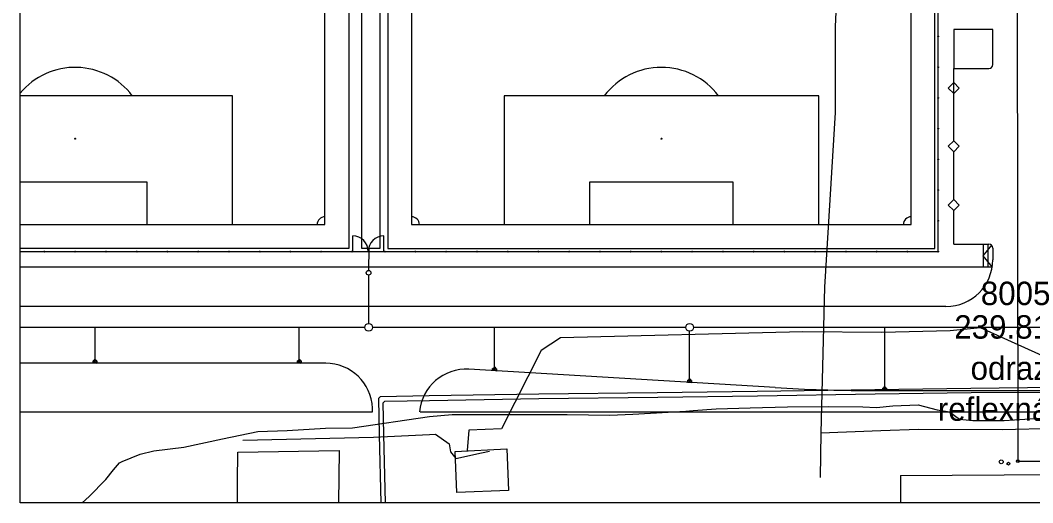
# Model space of a CAD drawing. Extents: x -264090 to -263500, y -1242327 to -1242030.
# Drawn here: x -264089.7 to -263959.9, y -1242326.6 to -1242264.8 of the extents above; entities that cross this region are included whole.
import ezdxf

# ---------------------------------------------------------------- set-up
doc = ezdxf.new("R2010")
doc.units = 0
for name, color, linetype in [('KFA_KOORD_SIT_a_IS_SEDA', 7, 'Continuous'), ('KFA_ZVS_BOD_CISLO', 7, 'Continuous'), ('KFA_ZVS_BOD_VYSKA', 7, 'Continuous'), ('KFA_ZVS_POPIS', 7, 'Continuous'), ('RAM_NA_TLAC', 7, 'Continuous')]:
    doc.layers.add(name, color=color, linetype=linetype)

msp = doc.modelspace()

# ---------------------------------------------------------------- linework, layer by layer
at = {"layer": 'KFA_KOORD_SIT_a_IS_SEDA'}
for p, q in [((-264047.57, -1242187.93), (-264047.57, -1242294.03)), ((-264050.62, -1242290.98), (-264050.62, -1242190.98)), ((-264039.52, -1242190.98), (-264039.52, -1242290.98)), ((-263975.52, -1242290.98), (-263975.52, -1242190.98)), ((-264045.93, -1242194.98), (-264045.93, -1242293.98)), ((-264043.53, -1242293.98), (-264043.53, -1242194.98)), ((-263984.63, -1242252.16), (-263985.27, -1242265.6)), ((-263972.07, -1242294.43), (-263972.07, -1242255.06)), ((-263961.97, -1242257), (-263961.85, -1242321.3)), ((-263985.27, -1242265.6), (-263985.24, -1242276.61)), ((-263972.13, -1242266.87), (-263972.01, -1242266.87)), ((-263972.07, -1242266.93), (-263972.07, -1242266.81)), ((-263965.07, -1242265.98), (-263970.07, -1242265.98)), ((-263965.07, -1242270.48), (-263965.07, -1242265.98)), ((-263972.13, -1242270.81), (-263972.01, -1242270.81)), ((-263972.07, -1242270.87), (-263972.07, -1242270.75)), ((-263970.06, -1242280.24), (-263970.07, -1242270.98)), ((-264062.46, -1242274.48), (-264089.66, -1242274.48)), ((-264062.46, -1242290.98), (-264062.46, -1242274.48)), ((-263987.36, -1242274.48), (-264027.68, -1242274.48)), ((-264027.68, -1242274.48), (-264027.68, -1242290.98)), ((-263987.36, -1242290.98), (-263987.36, -1242274.48)), ((-263972.13, -1242274.74), (-263972.01, -1242274.74)), ((-263972.07, -1242274.8), (-263972.07, -1242274.68)), ((-263985.24, -1242276.61), (-263986.63, -1242298.98)), ((-263972.13, -1242278.68), (-263972.01, -1242278.68)), ((-263972.07, -1242278.74), (-263972.07, -1242278.62)), ((-263972.13, -1242282.62), (-263972.01, -1242282.62)), ((-263972.07, -1242282.68), (-263972.07, -1242282.56)), ((-263970.07, -1242287.78), (-263970.07, -1242281.65)), ((-264089.66, -1242285.48), (-264073.46, -1242285.48)), ((-264073.46, -1242285.48), (-264073.46, -1242290.98)), ((-264016.68, -1242290.98), (-264016.68, -1242285.48)), ((-264016.68, -1242285.48), (-263998.36, -1242285.48)), ((-263998.36, -1242285.48), (-263998.36, -1242290.98)), ((-263972.13, -1242286.56), (-263972.01, -1242286.56)), ((-263972.07, -1242286.62), (-263972.07, -1242286.5)), ((-263970.07, -1242293.48), (-263970.07, -1242289.19)), ((-263972.13, -1242290.49), (-263972.01, -1242290.49)), ((-263972.07, -1242290.55), (-263972.07, -1242290.43)), ((-264089.66, -1242290.98), (-264050.62, -1242290.98)), ((-264039.52, -1242290.98), (-263975.52, -1242290.98)), ((-264047.07, -1242294.43), (-264047.07, -1242292.43)), ((-264043.07, -1242294.43), (-264043.07, -1242292.43)), ((-264047.57, -1242294.03), (-264089.66, -1242294.03)), ((-264089.66, -1242294.03), (-264089.66, -1242294.03)), ((-264089.66, -1242294.43), (-264045.12, -1242294.43)), ((-264086.5, -1242294.43), (-264086.62, -1242294.43)), ((-264086.56, -1242294.49), (-264086.56, -1242294.37)), ((-264082.56, -1242294.43), (-264082.68, -1242294.43)), ((-264082.62, -1242294.49), (-264082.62, -1242294.37)), ((-264078.62, -1242294.43), (-264078.74, -1242294.43)), ((-264078.68, -1242294.49), (-264078.68, -1242294.37)), ((-264074.68, -1242294.43), (-264074.8, -1242294.43)), ((-264074.74, -1242294.49), (-264074.74, -1242294.37)), ((-264070.74, -1242294.43), (-264070.86, -1242294.43)), ((-264070.8, -1242294.49), (-264070.8, -1242294.37)), ((-264066.8, -1242294.43), (-264066.92, -1242294.43)), ((-264066.86, -1242294.49), (-264066.86, -1242294.37)), ((-264062.86, -1242294.43), (-264062.98, -1242294.43)), ((-264062.92, -1242294.49), (-264062.92, -1242294.37)), ((-264058.92, -1242294.43), (-264059.04, -1242294.43)), ((-264058.98, -1242294.49), (-264058.98, -1242294.37)), ((-264054.99, -1242294.43), (-264055.11, -1242294.43)), ((-264055.05, -1242294.49), (-264055.05, -1242294.37)), ((-264051.05, -1242294.43), (-264051.17, -1242294.43)), ((-264051.11, -1242294.49), (-264051.11, -1242294.37)), ((-264047.11, -1242294.43), (-264047.23, -1242294.43)), ((-264047.17, -1242294.49), (-264047.17, -1242294.37)), ((-264045.93, -1242293.98), (-264043.53, -1242293.98)), ((-264045.57, -1242294.43), (-264044.57, -1242294.43)), ((-264045.12, -1242294.43), (-263972.07, -1242294.43)), ((-264045.02, -1242293.98), (-264045.03, -1242296.85)), ((-264042.91, -1242294.43), (-264043.03, -1242294.43)), ((-264042.97, -1242294.49), (-264042.97, -1242294.37)), ((-264038.97, -1242294.43), (-264039.09, -1242294.43)), ((-264039.03, -1242294.49), (-264039.03, -1242294.37)), ((-264035.03, -1242294.43), (-264035.15, -1242294.43)), ((-264035.09, -1242294.49), (-264035.09, -1242294.37)), ((-264031.09, -1242294.43), (-264031.21, -1242294.43)), ((-264031.15, -1242294.49), (-264031.15, -1242294.37)), ((-264027.15, -1242294.43), (-264027.27, -1242294.43)), ((-264027.21, -1242294.49), (-264027.21, -1242294.37)), ((-264023.21, -1242294.43), (-264023.33, -1242294.43)), ((-264023.27, -1242294.49), (-264023.27, -1242294.37)), ((-264019.27, -1242294.43), (-264019.39, -1242294.43)), ((-264019.33, -1242294.49), (-264019.33, -1242294.37)), ((-264015.34, -1242294.43), (-264015.46, -1242294.43)), ((-264015.4, -1242294.49), (-264015.4, -1242294.37)), ((-264011.4, -1242294.43), (-264011.52, -1242294.43)), ((-264011.46, -1242294.49), (-264011.46, -1242294.37)), ((-264007.46, -1242294.43), (-264007.58, -1242294.43)), ((-264007.52, -1242294.49), (-264007.52, -1242294.37)), ((-264003.52, -1242294.43), (-264003.64, -1242294.43)), ((-264003.58, -1242294.49), (-264003.58, -1242294.37)), ((-263999.58, -1242294.43), (-263999.7, -1242294.43)), ((-263999.64, -1242294.49), (-263999.64, -1242294.37)), ((-263995.64, -1242294.43), (-263995.76, -1242294.43)), ((-263995.7, -1242294.49), (-263995.7, -1242294.37)), ((-263991.7, -1242294.43), (-263991.82, -1242294.43)), ((-263991.76, -1242294.49), (-263991.76, -1242294.37)), ((-263987.76, -1242294.43), (-263987.88, -1242294.43)), ((-263987.82, -1242294.49), (-263987.82, -1242294.37)), ((-263983.82, -1242294.43), (-263983.94, -1242294.43)), ((-263983.88, -1242294.49), (-263983.88, -1242294.37)), ((-263979.89, -1242294.43), (-263980.01, -1242294.43)), ((-263979.95, -1242294.49), (-263979.95, -1242294.37)), ((-263975.95, -1242294.43), (-263976.07, -1242294.43)), ((-263976.01, -1242294.49), (-263976.01, -1242294.37)), ((-263972.13, -1242294.43), (-263972.01, -1242294.43)), ((-263972.07, -1242294.49), (-263972.07, -1242294.37)), ((-263970.07, -1242293.48), (-263965.57, -1242293.48)), ((-263966.31, -1242293.48), (-263966.31, -1242296.43)), ((-263965.68, -1242293.48), (-263965.68, -1242296.43)), ((-263965.07, -1242293.98), (-263965.07, -1242295.48)), ((-264045.03, -1242297.45), (-264045.03, -1242303.65)), ((-263986.63, -1242298.98), (-263987.11, -1242317.68)), ((-263971.07, -1242301.48), (-264089.66, -1242301.48)), ((-264045.53, -1242304.15), (-264089.66, -1242304.15)), ((-264080.08, -1242308.24), (-264080.08, -1242304.15)), ((-264053.91, -1242308.24), (-264053.91, -1242304.15)), ((-264004.4, -1242304.15), (-264044.53, -1242304.15)), ((-264028.9, -1242309.22), (-264028.89, -1242304.15)), ((-263989.39, -1242304.73), (-264020.46, -1242305.5)), ((-264003.9, -1242310.72), (-264003.9, -1242304.65)), ((-263954.41, -1242304.15), (-264003.4, -1242304.15)), ((-263979.27, -1242304.82), (-263989.39, -1242304.73)), ((-263970.54, -1242304.6), (-263979.27, -1242304.82)), ((-263978.91, -1242311.74), (-263978.91, -1242304.15)), ((-263966.62, -1242304.22), (-263970.54, -1242304.6)), ((-263946.96, -1242313.09), (-263966.62, -1242304.22)), ((-264020.46, -1242305.5), (-264022.91, -1242307.11)), ((-264022.91, -1242307.11), (-264028.02, -1242317.15)), ((-264080.33, -1242308.44), (-264079.83, -1242308.44)), ((-264080.33, -1242308.73), (-264080.33, -1242308.44)), ((-264080.33, -1242308.44), (-264079.83, -1242308.73)), ((-264080.33, -1242308.44), (-264079.83, -1242308.73)), ((-264079.83, -1242308.44), (-264080.33, -1242308.44)), ((-264079.83, -1242308.44), (-264079.83, -1242308.73)), ((-264079.83, -1242308.73), (-264079.83, -1242308.44)), ((-264054.16, -1242308.44), (-264053.66, -1242308.44)), ((-264054.16, -1242308.73), (-264054.16, -1242308.44)), ((-264054.16, -1242308.44), (-264053.66, -1242308.73)), ((-264054.16, -1242308.44), (-264053.66, -1242308.73)), ((-264053.66, -1242308.44), (-264054.16, -1242308.44)), ((-264053.66, -1242308.44), (-264053.66, -1242308.73)), ((-264053.66, -1242308.73), (-264053.66, -1242308.44)), ((-264050.53, -1242308.73), (-264089.66, -1242308.73)), ((-264079.83, -1242308.73), (-264080.33, -1242308.73)), ((-264053.66, -1242308.73), (-264054.16, -1242308.73)), ((-263992.94, -1242311.87), (-264032.17, -1242309.51)), ((-264032.17, -1242309.51), (-264032.17, -1242309.51)), ((-264029.16, -1242309.69), (-264029.14, -1242309.41)), ((-264028.66, -1242309.72), (-264029.16, -1242309.69)), ((-264029.14, -1242309.41), (-264028.65, -1242309.44)), ((-264029.14, -1242309.41), (-264028.66, -1242309.72)), ((-264029.14, -1242309.41), (-264028.66, -1242309.72)), ((-264028.65, -1242309.44), (-264029.14, -1242309.41)), ((-264028.65, -1242309.44), (-264028.66, -1242309.72)), ((-264028.66, -1242309.72), (-264028.65, -1242309.44)), ((-264004.16, -1242311.2), (-264004.15, -1242310.91)), ((-264003.66, -1242311.23), (-264004.16, -1242311.2)), ((-264004.15, -1242310.91), (-264003.65, -1242310.94)), ((-264004.15, -1242310.91), (-264003.66, -1242311.23)), ((-264004.15, -1242310.91), (-264003.66, -1242311.23)), ((-264003.65, -1242310.94), (-264004.15, -1242310.91)), ((-264003.65, -1242310.94), (-264003.66, -1242311.23)), ((-264003.66, -1242311.23), (-264003.65, -1242310.94)), ((-264008.06, -1242312.52), (-264023.23, -1242312.7)), ((-263995.27, -1242312.37), (-264008.06, -1242312.52)), ((-263980.16, -1242312.16), (-263995.27, -1242312.37)), ((-263980.94, -1242312.23), (-263857.33, -1242312.23)), ((-263967.86, -1242311.99), (-263980.16, -1242312.16)), ((-263980.14, -1242312.68), (-263967.84, -1242312.51)), ((-263979.16, -1242311.94), (-263978.66, -1242311.94)), ((-263979.16, -1242312.23), (-263979.16, -1242311.94)), ((-263979.16, -1242311.94), (-263978.66, -1242312.23)), ((-263979.16, -1242311.94), (-263978.66, -1242312.23)), ((-263978.66, -1242311.94), (-263979.16, -1242311.94)), ((-263978.66, -1242312.23), (-263979.16, -1242312.23)), ((-263978.66, -1242311.94), (-263978.66, -1242312.23)), ((-263978.66, -1242312.23), (-263978.66, -1242311.94)), ((-263956.22, -1242311.84), (-263967.86, -1242311.99)), ((-263967.84, -1242312.51), (-263955.67, -1242312.42)), ((-264043.54, -1242313.06), (-264043.78, -1242313.27)), ((-264043.78, -1242313.27), (-264043.67, -1242317.93)), ((-264037.28, -1242312.92), (-264043.54, -1242313.06)), ((-264043.16, -1242313.81), (-264042.95, -1242313.61)), ((-264043.1, -1242317.89), (-264043.16, -1242313.81)), ((-264042.95, -1242313.61), (-264037.23, -1242313.51)), ((-264023.23, -1242312.7), (-264037.28, -1242312.92)), ((-264037.23, -1242313.51), (-264023.21, -1242313.28)), ((-264023.21, -1242313.28), (-264007.99, -1242313.07)), ((-264007.99, -1242313.07), (-263995.2, -1242312.9)), ((-263995.2, -1242312.9), (-263980.14, -1242312.68)), ((-264089.66, -1242314.98), (-264044.53, -1242314.98)), ((-264044.53, -1242314.98), (-264044.53, -1242314.48)), ((-264038.44, -1242314.98), (-263836.4, -1242314.98)), ((-264011.19, -1242315.25), (-264004.4, -1242314.87)), ((-264004.4, -1242314.87), (-264003.44, -1242314.8)), ((-264003.44, -1242314.8), (-264000.5, -1242314.59)), ((-264000.5, -1242314.59), (-263996.15, -1242314.45)), ((-263996.15, -1242314.45), (-263991.36, -1242314.31)), ((-263991.36, -1242314.31), (-263986.12, -1242314.3)), ((-263986.12, -1242314.3), (-263981.72, -1242314.33)), ((-263981.72, -1242314.33), (-263979.98, -1242314.43)), ((-263979.98, -1242314.43), (-263977.86, -1242314.19)), ((-263977.86, -1242314.19), (-263974.61, -1242314.09)), ((-263974.61, -1242314.09), (-263972.17, -1242314.7)), ((-263972.17, -1242314.7), (-263970.63, -1242314.99)), ((-263970.63, -1242314.99), (-263969.31, -1242315.89)), ((-264047.11, -1242317.03), (-264037.23, -1242315.56)), ((-264037.23, -1242315.56), (-264034.31, -1242315.31)), ((-264034.31, -1242315.31), (-264029.89, -1242315.32)), ((-264029.89, -1242315.32), (-264024.65, -1242315.29)), ((-264024.65, -1242315.29), (-264019.6, -1242315.33)), ((-264019.6, -1242315.33), (-264014.13, -1242315.41)), ((-264014.13, -1242315.41), (-264011.19, -1242315.25)), ((-263969.31, -1242315.89), (-263967.63, -1242316.08)), ((-263967.63, -1242316.08), (-263963.59, -1242316.09)), ((-263963.59, -1242316.09), (-263956.5, -1242315.61)), ((-264063.75, -1242318.45), (-264059.23, -1242317.5)), ((-264059.23, -1242317.5), (-264055.45, -1242317.35)), ((-264055.45, -1242317.35), (-264050.57, -1242317.07)), ((-264050.57, -1242317.07), (-264047.11, -1242317.03)), ((-264032.17, -1242317.31), (-264032.39, -1242319.93)), ((-264028.02, -1242317.15), (-264032.17, -1242317.31)), ((-263987.11, -1242317.68), (-263987.17, -1242323.4)), ((-263987.11, -1242317.68), (-263979.4, -1242317.34)), ((-263979.4, -1242317.34), (-263974.58, -1242317.17)), ((-263974.58, -1242317.17), (-263963.87, -1242317.22)), ((-263963.87, -1242317.22), (-263943.25, -1242316.73)), ((-264068.7, -1242319.48), (-264063.75, -1242318.45)), ((-264061.14, -1242318.59), (-264044.39, -1242318.22)), ((-264044.39, -1242318.22), (-264037.22, -1242317.89)), ((-264043.67, -1242317.93), (-264043.45, -1242326.62)), ((-264042.86, -1242326.62), (-264043.1, -1242317.89)), ((-264037.22, -1242317.89), (-264036.44, -1242317.83)), ((-264036.44, -1242317.83), (-264034.73, -1242319.08)), ((-264034.73, -1242319.08), (-264034.52, -1242320.11)), ((-264074.3, -1242320.41), (-264072.53, -1242319.96)), ((-264072.53, -1242319.96), (-264068.7, -1242319.48)), ((-264061.82, -1242323.92), (-264061.79, -1242320.14)), ((-264061.79, -1242320.14), (-264048.82, -1242319.93)), ((-264048.82, -1242319.93), (-264048.87, -1242326.62)), ((-264034.52, -1242320.11), (-264033.86, -1242320.96)), ((-264033.95, -1242320.06), (-264027.34, -1242319.71)), ((-264033.72, -1242325.32), (-264033.95, -1242320.06)), ((-264033.86, -1242320.96), (-264030.57, -1242320.23)), ((-264030.57, -1242320.23), (-264029.56, -1242320)), ((-264027.34, -1242319.71), (-264027.11, -1242325.04)), ((-264077.73, -1242322.4), (-264076.93, -1242321.5)), ((-264076.93, -1242321.5), (-264076.59, -1242321.35)), ((-264076.59, -1242321.35), (-264074.3, -1242320.41)), ((-263961.85, -1242321.3), (-263870.44, -1242320.86)), ((-263961.85, -1242321.3), (-263961.85, -1242321.3)), ((-264078.68, -1242323.64), (-264077.73, -1242322.4)), ((-263976.89, -1242323.14), (-263880.39, -1242322.51)), ((-264080.85, -1242325.81), (-264078.68, -1242323.64)), ((-264061.84, -1242326.62), (-264061.82, -1242323.92)), ((-263976.89, -1242323.14), (-263976.87, -1242326.62)), ((-264027.11, -1242325.04), (-264033.72, -1242325.32)), ((-264081.72, -1242326.62), (-264080.85, -1242325.81))]:
    msp.add_line(p, q, dxfattribs=at)
for points in [[(-264042.57, -1242294.03), (-263972.47, -1242294.03), (-263972.47, -1242187.93), (-264042.57, -1242187.93)], [(-263970.07, -1242272.78), (-263969.36, -1242273.48), (-263970.07, -1242274.19), (-263970.77, -1242273.48)], [(-263970.07, -1242280.24), (-263969.36, -1242280.94), (-263970.07, -1242281.65), (-263970.77, -1242280.94)], [(-263970.07, -1242287.78), (-263969.36, -1242288.48), (-263970.07, -1242289.19), (-263970.77, -1242288.48)]]:
    msp.add_lwpolyline(points, close=True, dxfattribs=at)
for points in [[(-263970.07, -1242265.98), (-263970.07, -1242270.98), (-263965.57, -1242270.98)], [(-263965.21, -1242293.63), (-263966.35, -1242294.96), (-263965.14, -1242296.43)], [(-263965.14, -1242296.43), (-264089.66, -1242296.43)]]:
    msp.add_lwpolyline(points, dxfattribs=at)
for centre, radius in [((-263972.07, -1242266.87), 0.06), ((-263972.07, -1242270.81), 0.06), ((-263972.07, -1242274.74), 0.06), ((-263972.07, -1242278.68), 0.06), ((-264082.62, -1242279.98), 0.06), ((-264007.52, -1242279.98), 0.06), ((-263972.07, -1242282.62), 0.06), ((-263972.07, -1242286.56), 0.06), ((-263972.07, -1242290.49), 0.06), ((-264086.56, -1242294.43), 0.06), ((-264082.62, -1242294.43), 0.06), ((-264078.68, -1242294.43), 0.06), ((-264074.74, -1242294.43), 0.06), ((-264070.8, -1242294.43), 0.06), ((-264066.86, -1242294.43), 0.06), ((-264062.92, -1242294.43), 0.06), ((-264058.98, -1242294.43), 0.06), ((-264055.05, -1242294.43), 0.06), ((-264051.11, -1242294.43), 0.06), ((-264047.17, -1242294.43), 0.06), ((-264042.97, -1242294.43), 0.06), ((-264039.03, -1242294.43), 0.06), ((-264035.09, -1242294.43), 0.06), ((-264031.15, -1242294.43), 0.06), ((-264027.21, -1242294.43), 0.06), ((-264023.27, -1242294.43), 0.06), ((-264019.33, -1242294.43), 0.06), ((-264015.4, -1242294.43), 0.06), ((-264011.46, -1242294.43), 0.06), ((-264007.52, -1242294.43), 0.06), ((-264003.58, -1242294.43), 0.06), ((-263999.64, -1242294.43), 0.06), ((-263995.7, -1242294.43), 0.06), ((-263991.76, -1242294.43), 0.06), ((-263987.82, -1242294.43), 0.06), ((-263983.88, -1242294.43), 0.06), ((-263979.95, -1242294.43), 0.06), ((-263976.01, -1242294.43), 0.06), ((-263972.07, -1242294.43), 0.06), ((-264045.03, -1242297.15), 0.3), ((-264045.03, -1242304.15), 0.5), ((-264003.9, -1242304.15), 0.5), ((-264080.08, -1242308.34), 0.1), ((-264053.91, -1242308.34), 0.1), ((-264028.89, -1242309.32), 0.1), ((-264003.9, -1242310.82), 0.1), ((-263978.91, -1242311.84), 0.1), ((-263963.98, -1242321.38), 0.25), ((-263963.07, -1242321.61), 0.179), ((-263961.85, -1242321.3), 0.179)]:
    msp.add_circle(centre, radius, dxfattribs=at)
for centre, radius, start, end in [((-264082.62, -1242279.98), 9.15, 36.9482, 140.3046), ((-264007.52, -1242279.98), 9.15, 36.9482, 143.0518), ((-263965.57, -1242270.48), 0.5, 270, 0), ((-264082.62, -1242279.98), 0.0303, 90, 270), ((-264082.62, -1242279.98), 0.0303, 270, 90), ((-264007.52, -1242279.98), 0.0303, 90, 270), ((-264007.52, -1242279.98), 0.0303, 270, 90), ((-264050.62, -1242290.98), 1, 90, 180), ((-264039.52, -1242290.98), 1, 0, 90), ((-263975.52, -1242290.98), 1, 90, 180), ((-264047.07, -1242294.43), 2, 0, 90), ((-264043.07, -1242294.43), 2, 90, 180), ((-263965.57, -1242293.98), 0.5, 0, 90), ((-263971.07, -1242295.48), 6, 270, 0), ((-264050.56, -1242314.77), 6.04, 2.7254, 89.7124), ((-264032.53, -1242315.5), 6, 86.5602, 175.0205), ((-263980.94, -1242112.23), 200, 266.5602, 270)]:
    msp.add_arc(centre, radius, start, end, dxfattribs=at)
at = {"layer": 'RAM_NA_TLAC'}
msp.add_lwpolyline([(-264089.66, -1242029.62), (-263499.66, -1242029.62), (-263499.66, -1242326.62), (-264089.66, -1242326.62)], close=True, dxfattribs=at)

# ---------------------------------------------------------------- texts
at = {"layer": 'KFA_ZVS_BOD_CISLO'}
msp.add_text('8005', height=3, dxfattribs=at).set_placement((-263966.6, -1242301.29))
at = {"layer": 'KFA_ZVS_BOD_VYSKA'}
msp.add_text('239.818', height=3, dxfattribs=at).set_placement((-263970, -1242305.59))
at = {"layer": 'KFA_ZVS_POPIS'}
for s, p in [('odrazná', (-263967.91, -1242310.87)), ('reflexná fólia', (-263972.1, -1242316.12))]:
    msp.add_text(s, height=3, dxfattribs=at).set_placement(p)

doc.saveas('drawing.dxf')
